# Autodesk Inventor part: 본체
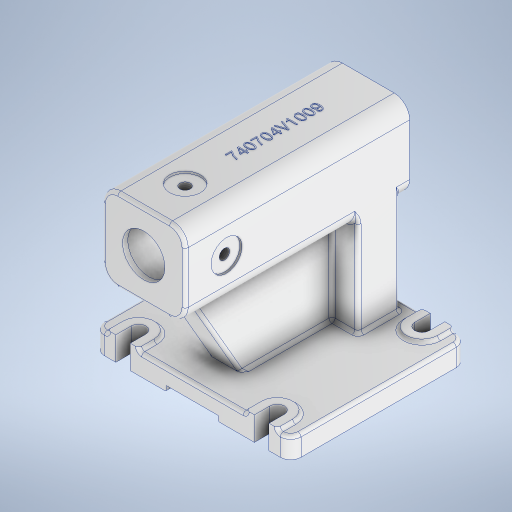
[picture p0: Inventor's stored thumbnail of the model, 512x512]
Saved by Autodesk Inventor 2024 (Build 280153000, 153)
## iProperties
Created: 2024-07
Part Number: 본체
Material: 알루미늄 6061
Document SubType Name: Modeling
Designer: com
Density: 2.7 g/cm^3
Appearance: 알루미늄 - 평지
Mass: 5575.12 g
Surface Area: 2201.89 cm^2
Volume: 2064.86 cm^3
Author: com
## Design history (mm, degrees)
sketch "스케치1"
  geometry: L1 (-85, -95)-(85, -95); L2 (85, -95)-(85, 95); L3 (85, 95)-(-85, 95); L4 (-85, 95)-(-85, -95); L5 (-85, -95)-(85, 95); L6 (85, -95)-(-85, 95); 1 further point
  constraints: 12 end point, 2 midpoint, 2 parallel, 1 horizontal, 1 perpendicular
  dimensions: "d0" = 170 distance of L3.end L2.end; "d1" = 190 distance of L2.end L1.end
extrude "돌출1" new body sketch "스케치1" distance "d2" = 20; taper "d3" = 0 deg
node "작업 평면1"
sketch "스케치3"
  geometry: L1 (-85, 95)-(-85, -95) reference; L2 (-85, 0)-(-75, 0); L3 (-75, 0)-(-75, -40); L4 (-75, -40)-(-35, -40); L5 (-35, -40)-(-35, -15); L6 (-35, -15)-(53.838, -15); L7 (53.838, -15)-(53.838, 0); L8 (53.838, 0)-(-75, 0); L9 (-35, 15)-(53.838, 15); L10 (53.838, 15)-(53.838, 0); L11 (-35, 40)-(-35, 15); L12 (-75, 40)-(-35, 40); L13 (-75, 0)-(-75, 40)
  constraints: 24 end point, 5 perpendicular, 4 symmetric about line, 2 horizontal, 1 midpoint, 1 point on line
  dimensions: "d9" = 10 distance of L2.start L2.end; "d10" = 40 distance of L2.end L3.end; "d11" = 40 distance of L3.end L4.end; "d12" = 25 distance of L4.end L5.end
sketch "스케치4"
  geometry: L1 (-132, 110)-(85, 110); L2 (85, 110)-(85, 190); L3 (85, 190)-(-132, 190); L4 (-132, 190)-(-132, 110); L5 (-132, 110)-(85, 190); L6 (85, 110)-(-132, 190); L7 (-85, 0)-(85, 0) reference; L8 (85, 0)-(85, 20) reference; 2 further points
  constraints: 12 end point, 2 midpoint, 2 parallel, 1 horizontal, 1 perpendicular
  dimensions: "d13" = 217 distance of L3.end L2.end; "d14" = 80 distance of L1.end L2.end; "d15" = 150 distance from line of L7 point (-23.5, 150)
extrude "돌출2" join sketch "스케치4" stored distance "d17" = 80; taper "d18" = 0 deg
extrude "돌출3" join sketch "스케치3" stored distance "d19" = 80; taper "d20" = 0 deg
sketch "스케치5"
  geometry: L1 (85, 20)-(-85, 20) reference; L2 (-53.838, 20)-(-105.8, 110); L3 (35, 110)-(-132, 110) reference; 2 further points
  constraints: 3 point on line, 2 end point
  dimensions: "d21" = 120 deg angle of L2 L1
feature "리브1" sketch "스케치5" dims "d22" = 1, "d23" = 30, "d24" = 0, "d25" = 0, "d26" = 1, "d27" = 1
sketch "스케치6"
  geometry: C1 r 20.5 at (-40, 40); 2 further points
  constraints: 1 centre point, 1 coincident
  dimensions: "d28" = 41 diameter of C1
extrude "돌출4" cut sketch "스케치6" extent not by distance; stored distance "d29" = 0; taper "d30" = 0 deg
sketch "스케치8"
  geometry: L1 (0, -133)-(0, 133) reference; L2 (85, -95)-(85, 95) reference; L3 (70, 74)-(85, 74); L4 (70, 60)-(85, 60); L5 (85, 74)-(85, 60); L6 (70, 82)-(85, 82); L7 (70, 52)-(85, 52); L8 (85, 82)-(85, 52); A1 r 15 centre (70, 67) between (55, 67) and (85, 67); A2 r 7 centre (70, 67) between (77, 67) and (63, 67); 2 further points
  constraints: 12 end point, 8 point on circle, 4 perpendicular, 4 point on line, 2 centre point, 2 collinear, 1 coincident, 1 midpoint, 1 tangent
  dimensions: "d49" = 67 vertical distance of A1.centre point (85, 0); "d110" = 15 distance from line of L5 A1.centre; "d111" = 14 diameter of A2; "d112" = 14 distance between parallel lines of L3 L4; "d113" = 7 distance from line of A1.centre L4
extrude "돌출6" cut sketch "스케치8" distance "d40" = 212; taper "d41" = 0 deg
extrude "돌출7" join sketch "스케치8" distance "d42" = 3; taper "d43" = 0 deg
fillet "모깎기1" dims "d53" = 15
fillet "모깎기6" dims "d62" = 3
fillet "모깎기2" dims "d83" = 3
sketch "스케치9"
  geometry: L1 (-5, 85)-(5, 85); L2 (5, 85)-(5, 35); L3 (5, 35)-(-5, 35); L4 (-5, 35)-(-5, 85); L5 (-5, 85)-(5, 35); L6 (5, 85)-(-5, 35); 1 further point
  constraints: 12 end point, 2 midpoint, 2 parallel, 1 horizontal, 1 perpendicular
  dimensions: "d55" = 10 distance of L2.end L3.end; "d56" = 50 distance of L1.end L2.end
extrude "돌출8" cut sketch "스케치9" extent not by distance; stored distance "d57" = 0; taper "d58" = 0 deg
fillet "모깎기3" dims "d59" = 10
fillet "모깎기4" dims "d60" = 3
fillet "모깎기5" dims "d61" = 3
sketch "스케치10"
  geometry: C1 r 20.5 at (37, 25) reference; C2 r 26 at (37, 25); 1 further point
  constraints: 1 centre point, 1 coincident
  dimensions: "d64" = 52 diameter of C2
extrude "돌출9" cut sketch "스케치10" distance "d65" = 212; taper "d66" = 0 deg
sketch "스케치11"
  geometry: 3 further points
hole "구멍1" sketch "스케치11" at (69, 25) diameter "d68" = 4.917; stored, may be unused: countersink angle "d72" = 90 deg, drill point angle "d74" = 118 deg; dims "d69" = 12, "d70" = 4, "d71" = 2, "d73" = 14
chamfer "모따기1" distance "d78" = 2; stored, may be unused: second distance "d79" = 2, angle "d80" = 30 deg
fillet "모깎기8" dims "d81" = 1
fillet "모깎기9" dims "d82" = 2
sketch "스케치12"
  geometry: C1 r 15 at (177, 25); 1 further point
  constraints: 1 centre point
  dimensions: "d85" = 30 diameter of C1
extrude "돌출10" cut sketch "스케치12" distance "d86" = 2; taper "d87" = 0 deg
sketch "스케치13"
  geometry: C1 r 15 at (0, 0) reference; 2 further points
  constraints: 1 coincident
hole "구멍2" sketch "스케치13" at (0, 0) diameter "d88" = 10.106; stored, may be unused: countersink angle "d92" = 90 deg, drill point angle "d94" = 118 deg; dims "d89" = 24, "d90" = 4, "d91" = 2, "d93" = 32.3
sketch "스케치14"
  geometry: L1 (0, 0)-(0, 50) reference; 2 further points
  constraints: 1 horizontal alignment, 1 other
  dimensions: "d101" = 90 distance from line of L1 point (90, 25)
feature "엠보싱1" sketch "스케치14" dims "d9" = 10, "d10" = 40, "d11" = 40, "d12" = 25, "d102" = 0.5, "d103" = 0
chamfer "모따기2" distance "d104" = 1; stored, may be unused: second distance "d105" = 2, angle "d106" = 45 deg
chamfer "모따기3" distance "d107" = 1; stored, may be unused: second distance "d108" = 2, angle "d109" = 45 deg
feature "ˠ耀ˢ耀ˤ耀˦耀˨耀˪耀ˬ耀ˮ耀" dims "d0" = 170, "d1" = 190, "d2" = 20, "d3" = 0, "d9" = 10, "d10" = 40, "d11" = 40, "d12" = 25, "d13" = 217, "d14" = 80, "d15" = 150, "d17" = 80, "d18" = 0, "d19" = 80, "d20" = 0, "d21" = 120 deg, "d22" = 1, "d23" = 30, "d24" = 0, "d25" = 0, "d26" = 1, "d27" = 1, "d28" = 41, "d29" = 0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
node "솔리드1"
pattern_linear "직사각형 패턴2" dims "d52" = 134
mirror "미러2"
pattern_circular "원형 패턴1" dims angle "d76" = 360 deg
pattern_circular "원형 패턴2" dims angle "d96" = 90 deg
pattern_circular "원형 패턴3" dims angle "d99" = 270 deg
feature "A9D066F2-1C7D-4E18-AEED-F7BC21143FA4" dims "d68" = 4.917, "d69" = 12, "d70" = 4, "d71" = 2, "d72" = 90 deg, "d73" = 14, "d74" = 118 deg
